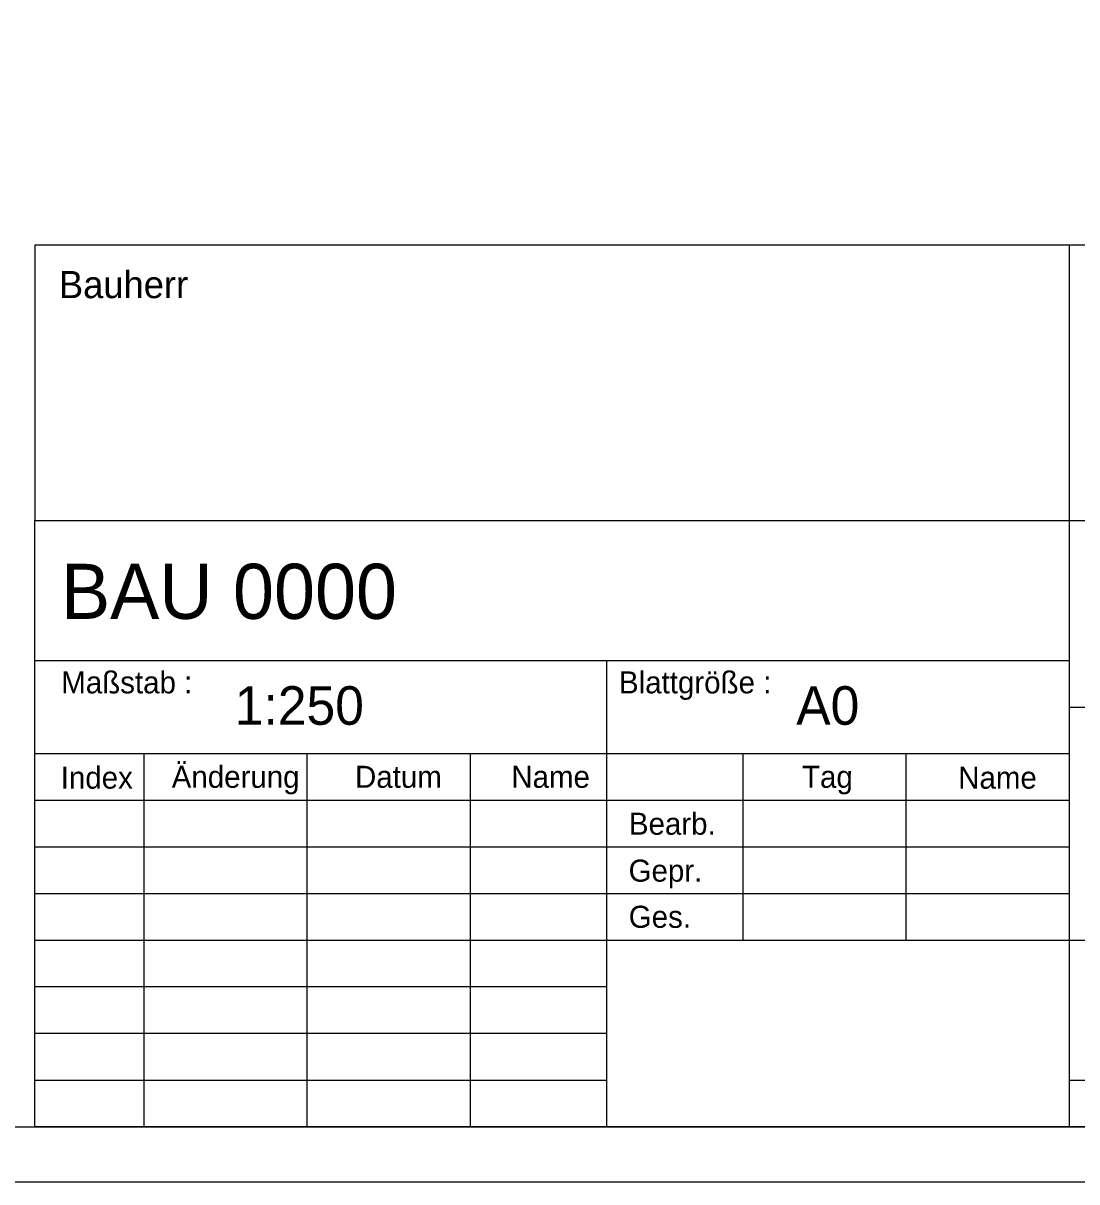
# Model space of a CAD drawing. Extents: x 0 to 297, y 0 to 210.
# Drawn here: x 251.26 to 275.16, y 0 to 26.28 of the extents above; entities that cross this region are included whole.
import ezdxf

# ---------------------------------------------------------------- set-up
doc = ezdxf.new("R2010")
doc.units = 0
doc.layers.add('90_Plankopf', color=7, linetype='Continuous')

msp = doc.modelspace()

# ---------------------------------------------------------------- linework, layer by layer
at = {"layer": '90_Plankopf'}
for p, q in [((296, 21.248), (251.53, 21.248)), ((251.53, 21.248), (251.53, 14.998)), ((275, 14.998), (275, 21.248)), ((251.53, 14.998), (296, 14.998)), ((251.53, 1.25), (251.53, 14.998)), ((251.53, 14.998), (296, 14.998)), ((275, 1.25), (275, 14.998)), ((251.53, 11.825), (275, 11.825)), ((264.5, 1.25), (264.5, 11.825)), ((275, 10.768), (296, 10.768)), ((251.53, 9.718), (275, 9.718)), ((254.001, 9.71), (254.001, 1.25)), ((257.707, 1.25), (257.707, 9.71)), ((261.412, 1.25), (261.412, 9.71)), ((267.589, 9.71), (267.589, 5.48)), ((271.295, 5.48), (271.295, 9.71)), ((251.53, 8.658), (275, 8.658)), ((251.53, 7.595), (275, 7.595)), ((251.53, 6.538), (275, 6.538)), ((251.53, 5.48), (275, 5.48)), ((251.53, 5.48), (275, 5.48)), ((264.5, 5.48), (275, 5.48)), ((275, 5.48), (296, 5.48)), ((264.5, 4.423), (251.53, 4.423)), ((264.5, 3.365), (251.53, 3.365)), ((251.53, 2.308), (264.5, 2.308)), ((275, 2.308), (296, 2.308)), ((296, 1.25), (251.53, 1.25)), ((251.53, 1.25), (264.5, 1.25)), ((254.45, 1.25), (296, 1.25)), ((254.45, 1.25), (296, 1.25))]:
    msp.add_line(p, q, dxfattribs=at)
for points in [[(0, 0), (297.25, 0), (297.25, 210.25), (0, 210.25)], [(6.25, 1.25), (296, 1.25), (296, 209), (6.25, 209)]]:
    msp.add_lwpolyline(points, close=True, dxfattribs=at)

# ---------------------------------------------------------------- texts
for s, height, p in [('Bauherr', 0.6159, (252.076, 20.044)), ('BAU 0000      ', 1.25, (252.123, 12.769)), ('Maßstab :', 0.5, (252.129, 11.079)), ('Blattgröße :', 0.49998, (264.779, 11.079)), ('1:250    ', 0.875, (256.065, 10.367)), ('A0       ', 0.875, (268.8, 10.367)), ('Änderung', 0.5, (254.634, 8.937)), ('Index', 0.5, (252.117, 8.918)), ('Datum', 0.5, (258.792, 8.937)), ('Name', 0.5, (262.337, 8.937)), ('Tag', 0.5, (268.931, 8.937)), ('Name', 0.5, (272.473, 8.918)), ('Bearb.', 0.5, (265.004, 7.873)), ('Gepr.', 0.5, (264.997, 6.808)), ('Ges.', 0.5, (265.001, 5.762))]:
    msp.add_text(s, height=height, dxfattribs=at).set_placement(p)

doc.saveas('drawing.dxf')
